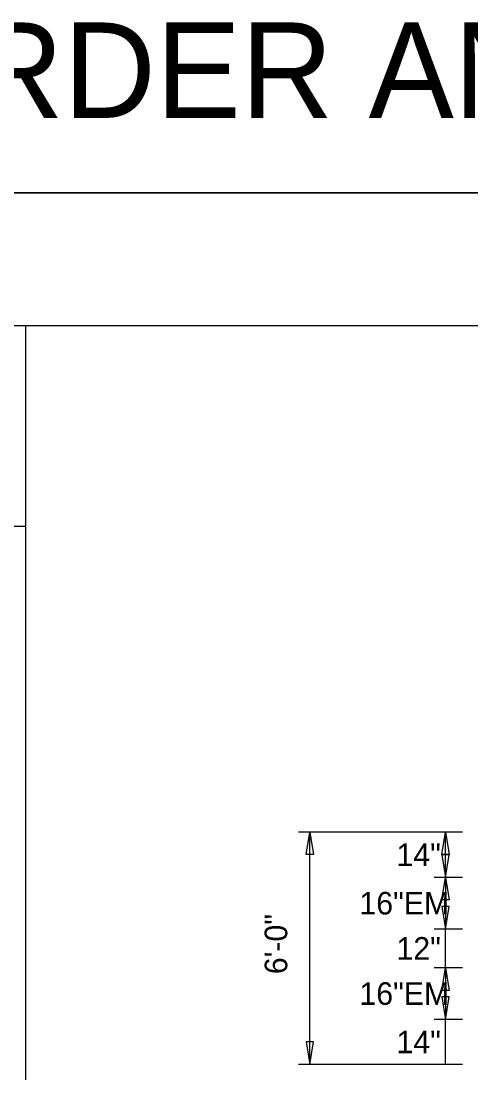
# Model space of a CAD drawing. Extents: x 2149934 to 2150188, y 145113 to 145238.
# Drawn here: x 2150076.2 to 2150087.81, y 145197.23 to 145224.38 of the extents above; entities that cross this region are included whole.
import ezdxf

# ---------------------------------------------------------------- set-up
doc = ezdxf.new("R2010")
doc.units = 0
for name, color, linetype in [('BORDER', 7, 'Continuous'), ('GSDIMS', 7, 'Continuous'), ('Level 1', 7, 'Continuous'), ('PDF', 7, 'Continuous'), ('TEXT', 7, 'Continuous')]:
    doc.layers.add(name, color=color, linetype=linetype)

msp = doc.modelspace()

# ---------------------------------------------------------------- linework, layer by layer
at = {"layer": 'BORDER'}
for p, q in [((2150010.458, 145219.948), (2150174.061, 145219.948)), ((2150171.536, 145216.512), (2150017.557, 145216.512))]:
    msp.add_line(p, q, dxfattribs=at)
at = {"layer": 'GSDIMS'}
for p, q in [((2150084.091, 145203.445), (2150083.362, 145203.445)), ((2150083.654, 145197.445), (2150083.654, 145203.445)), ((2150087.591, 145203.445), (2150084.091, 145203.445)), ((2150087.591, 145203.445), (2150086.862, 145203.445)), ((2150087.154, 145202.275), (2150087.154, 145203.445)), ((2150087.591, 145202.275), (2150086.862, 145202.275)), ((2150087.591, 145202.275), (2150086.862, 145202.275)), ((2150087.154, 145202.275), (2150087.154, 145200.942)), ((2150087.591, 145200.942), (2150086.862, 145200.942)), ((2150087.591, 145200.942), (2150086.862, 145200.942)), ((2150087.154, 145199.942), (2150087.154, 145200.942)), ((2150087.591, 145199.942), (2150086.862, 145199.942)), ((2150087.591, 145199.942), (2150086.862, 145199.942)), ((2150087.154, 145199.942), (2150087.154, 145198.609)), ((2150087.591, 145198.609), (2150086.862, 145198.609)), ((2150087.591, 145198.609), (2150086.862, 145198.609)), ((2150087.154, 145197.445), (2150087.154, 145198.609)), ((2150084.091, 145197.445), (2150083.362, 145197.445)), ((2150087.591, 145197.445), (2150084.091, 145197.445)), ((2150087.591, 145197.445), (2150086.862, 145197.445))]:
    msp.add_line(p, q, dxfattribs=at)
for points in [[(2150083.654, 145203.445), (2150083.751, 145202.862), (2150083.556, 145202.862)], [(2150087.154, 145203.445), (2150087.251, 145202.862), (2150087.056, 145202.862)], [(2150087.154, 145202.275), (2150087.251, 145202.859), (2150087.056, 145202.859)], [(2150087.154, 145202.275), (2150087.251, 145201.692), (2150087.056, 145201.692)], [(2150087.154, 145200.942), (2150087.251, 145201.525), (2150087.056, 145201.525)], [(2150087.154, 145199.942), (2150087.251, 145199.359), (2150087.056, 145199.359)], [(2150087.154, 145198.609), (2150087.251, 145199.192), (2150087.056, 145199.192)], [(2150083.654, 145197.445), (2150083.751, 145198.028), (2150083.556, 145198.028)]]:
    msp.add_lwpolyline(points, close=True, dxfattribs=at)
at = {"layer": 'Level 1'}
for p, q in [((2150076.316, 145216.512), (2150076.316, 145117.388)), ((2150062.21, 145211.34), (2150076.316, 145211.34))]:
    msp.add_line(p, q, dxfattribs=at)
at = {"layer": 'PDF'}
msp.add_lwpolyline([(2150010.458, 145114.088), (2150174.061, 145114.088), (2150174.061, 145219.948), (2150010.458, 145219.948)], close=True, dxfattribs=at)

# ---------------------------------------------------------------- texts
at = {"layer": 'GSDIMS'}
for s, p in [('14"', (2150085.889, 145202.569)), ('16"EM', (2150084.933, 145201.317)), ('12"', (2150085.889, 145200.15)), ('16"EM', (2150084.933, 145198.984)), ('14"', (2150085.889, 145197.735))]:
    msp.add_text(s, height=0.5833, dxfattribs=at).set_placement(p)
msp.add_text('6\'-0"', height=0.5833, rotation=90, dxfattribs=at).set_placement((2150083.07, 145199.777))
at = {"layer": 'TEXT'}
msp.add_text('BORDER AND REPORT 70 SCALE', height=2.46401, dxfattribs=at).set_placement((2150070.157, 145221.883))

doc.saveas('drawing.dxf')
